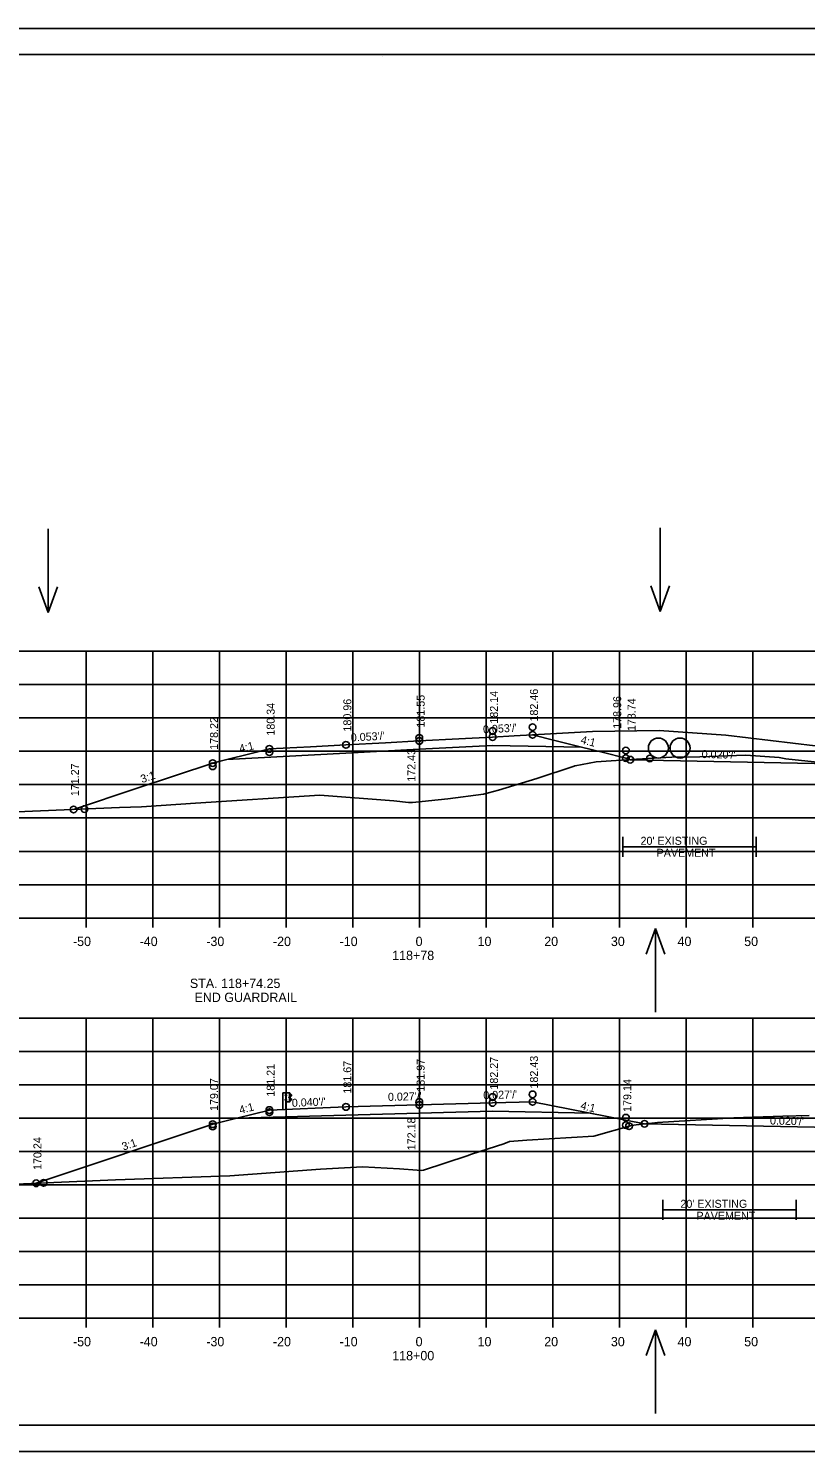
# Model space of a CAD drawing. Extents: x 915787 to 919910, y 133456 to 136717.
# Drawn here: x 916355.3 to 916471.9, y 135589.4 to 135802.7 of the extents above; entities that cross this region are included whole.
import ezdxf

# ---------------------------------------------------------------- set-up
doc = ezdxf.new("R2010")
doc.units = 0
for name, color, linetype in [('R_Axis', 7, 'Continuous'), ('R_Axis Annot', 7, 'Continuous'), ('R_Border', 7, 'Continuous'), ('R_Drive', 7, 'Continuous'), ('R_Exist Surface', 7, 'Continuous'), ('R_Exist Surface Annot', 7, 'Continuous'), ('R_Fin Surface', 7, 'Continuous'), ('R_Grid', 7, 'Continuous'), ('R_No Plot', 7, 'Continuous'), ('R_Proposed Road', 7, 'Continuous'), ('R_Water', 7, 'Continuous'), ('R_Water Annot', 7, 'Continuous'), ('R_Xsect Elev', 7, 'Continuous'), ('R_Xsect Slope', 7, 'Continuous')]:
    doc.layers.add(name, color=color, linetype=linetype)

msp = doc.modelspace()

# ---------------------------------------------------------------- linework, layer by layer
at = {"layer": 'R_Axis'}
for p, q in [((916273.98, 135669.39), (916553.98, 135669.39)), ((916363.98, 135667.99), (916363.98, 135669.39)), ((916373.98, 135667.99), (916373.98, 135669.39)), ((916383.98, 135667.99), (916383.98, 135669.39)), ((916393.98, 135667.99), (916393.98, 135669.39)), ((916403.98, 135667.99), (916403.98, 135669.39)), ((916413.98, 135667.99), (916413.98, 135669.39)), ((916423.98, 135667.99), (916423.98, 135669.39)), ((916433.98, 135667.99), (916433.98, 135669.39)), ((916443.98, 135667.99), (916443.98, 135669.39)), ((916453.98, 135667.99), (916453.98, 135669.39)), ((916463.98, 135667.99), (916463.98, 135669.39)), ((916273.98, 135609.39), (916553.98, 135609.39)), ((916363.98, 135607.99), (916363.98, 135609.39)), ((916373.98, 135607.99), (916373.98, 135609.39)), ((916383.98, 135607.99), (916383.98, 135609.39)), ((916393.98, 135607.99), (916393.98, 135609.39)), ((916403.98, 135607.99), (916403.98, 135609.39)), ((916413.98, 135607.99), (916413.98, 135609.39)), ((916423.98, 135607.99), (916423.98, 135609.39)), ((916433.98, 135607.99), (916433.98, 135609.39)), ((916443.98, 135607.99), (916443.98, 135609.39)), ((916453.98, 135607.99), (916453.98, 135609.39)), ((916463.98, 135607.99), (916463.98, 135609.39))]:
    msp.add_line(p, q, dxfattribs=at)
at = {"layer": 'R_Border'}
for p, q in [((916255.98, 135798.85), (916572.16, 135798.85)), ((916408.5, 135798.59), (916408.5, 135798.59)), ((916408.5, 135798.59), (916408.5, 135798.59)), ((916572.16, 135593.39), (916255.98, 135593.39))]:
    msp.add_line(p, q, dxfattribs=at)
at = {"layer": 'R_Drive'}
for q in [(916449.96, 135697.48), (916512.45, 135690.52)]:
    msp.add_line((916459.93, 135696.82), q, dxfattribs=at)
msp.add_lwpolyline([(916449.96, 135697.48), (916439.96, 135697.33), (916430.97, 135696.85)], dxfattribs=at)
at = {"layer": 'R_Exist Surface'}
for points in [[(916341.71, 135684.82), (916369.01, 135685.94), (916372.31, 135686.06), (916380.38, 135686.59), (916399.06, 135687.81), (916410.13, 135686.94), (916412.37, 135686.71), (916412.96, 135686.72), (916418.26, 135687.27), (916423.62, 135687.95), (916425.87, 135688.55), (916431.58, 135690.33), (916437.22, 135692.17), (916437.3, 135692.21), (916437.36, 135692.21), (916440.52, 135692.82), (916446.54, 135693.2), (916451.84, 135693.5), (916456.07, 135693.58), (916462.94, 135693.79), (916467.97, 135693.44), (916468.97, 135693.27), (916474.14, 135692.7)], [(916352.33, 135629.42), (916358.01, 135629.71), (916368.41, 135630.12), (916385.56, 135630.76), (916399.15, 135631.73), (916405.45, 135632.11), (916410.99, 135631.77), (916413.67, 135631.6), (916414.29, 135631.55), (916414.59, 135631.61), (916421.15, 135633.73), (916421.78, 135633.97), (916426.64, 135635.53), (916427.48, 135635.87), (916430.12, 135636.07), (916440.13, 135636.67), (916445.82, 135638.29), (916446.51, 135638.41), (916449.29, 135638.7), (916449.31, 135638.71), (916449.7, 135638.73), (916461.13, 135639.46), (916468.49, 135639.67), (916472.46, 135639.77)]]:
    msp.add_lwpolyline(points, dxfattribs=at)
at = {"layer": 'R_Exist Surface Annot'}
for p, q in [((916444.52, 135681.57), (916444.52, 135678.57)), ((916464.52, 135681.57), (916464.52, 135678.57)), ((916444.52, 135680.07), (916464.52, 135680.07)), ((916450.51, 135627.15), (916450.51, 135624.15)), ((916450.51, 135625.65), (916470.5, 135625.65)), ((916470.5, 135627.15), (916470.5, 135624.15))]:
    msp.add_line(p, q, dxfattribs=at)
at = {"layer": 'R_Fin Surface'}
for points in [[(916362.11, 135685.66), (916371.66, 135688.84), (916382.97, 135692.61), (916384.11, 135692.9), (916385.11, 135693.15), (916388.56, 135694.01), (916391.47, 135694.74), (916397.66, 135695.08), (916402.97, 135695.35), (916408.89, 135695.68), (916413.97, 135695.94), (916419.89, 135696.27), (916424.97, 135696.53), (916428.21, 135696.71), (916430.97, 135696.85), (916434.32, 135696.01), (916438.32, 135695.01), (916441.38, 135694.25), (916444.97, 135693.35), (916445.27, 135693.25), (916445.62, 135693.13), (916478.28, 135692.48)], [(916385.11, 135693.15), (916402.97, 135694.1), (916413.97, 135694.69), (916424.97, 135695.28), (916438.32, 135695.01)], [(916356.48, 135629.63), (916382.97, 135638.47), (916386.57, 135639.37), (916391.47, 135640.61), (916402.97, 135641.07), (916413.97, 135641.37), (916424.97, 135641.67), (916430.97, 135641.83), (916447.75, 135638.54), (916493.67, 135637.62)], [(916386.57, 135639.37), (916402.97, 135639.82), (916413.97, 135640.12), (916424.97, 135640.42), (916439.68, 135640.12)]]:
    msp.add_lwpolyline(points, dxfattribs=at)
at = {"layer": 'R_Grid'}
for p, q in [((916273.98, 135709.39), (916553.98, 135709.39)), ((916363.98, 135669.39), (916363.98, 135709.39)), ((916373.98, 135669.39), (916373.98, 135709.39)), ((916383.98, 135669.39), (916383.98, 135709.39)), ((916393.98, 135669.39), (916393.98, 135709.39)), ((916403.98, 135669.39), (916403.98, 135709.39)), ((916413.98, 135669.39), (916413.98, 135709.39)), ((916423.98, 135669.39), (916423.98, 135709.39)), ((916433.98, 135669.39), (916433.98, 135709.39)), ((916443.98, 135669.39), (916443.98, 135709.39)), ((916453.98, 135669.39), (916453.98, 135709.39)), ((916463.98, 135669.39), (916463.98, 135709.39)), ((916273.98, 135704.39), (916553.98, 135704.39)), ((916273.98, 135699.39), (916553.98, 135699.39)), ((916273.98, 135694.39), (916553.98, 135694.39)), ((916273.98, 135689.39), (916553.98, 135689.39)), ((916273.98, 135684.39), (916553.98, 135684.39)), ((916273.98, 135679.39), (916553.98, 135679.39)), ((916273.98, 135674.39), (916553.98, 135674.39)), ((916273.98, 135669.39), (916553.98, 135669.39)), ((916273.98, 135654.39), (916553.98, 135654.39)), ((916363.98, 135609.39), (916363.98, 135654.39)), ((916373.98, 135609.39), (916373.98, 135654.39)), ((916383.98, 135609.39), (916383.98, 135654.39)), ((916393.98, 135609.39), (916393.98, 135654.39)), ((916403.98, 135609.39), (916403.98, 135654.39)), ((916413.98, 135609.39), (916413.98, 135654.39)), ((916423.98, 135609.39), (916423.98, 135654.39)), ((916433.98, 135609.39), (916433.98, 135654.39)), ((916443.98, 135609.39), (916443.98, 135654.39)), ((916453.98, 135609.39), (916453.98, 135654.39)), ((916463.98, 135609.39), (916463.98, 135654.39)), ((916273.98, 135649.39), (916553.98, 135649.39)), ((916273.98, 135644.39), (916553.98, 135644.39)), ((916273.98, 135639.39), (916553.98, 135639.39)), ((916273.98, 135634.39), (916553.98, 135634.39)), ((916273.98, 135629.39), (916553.98, 135629.39)), ((916273.98, 135624.39), (916553.98, 135624.39)), ((916273.98, 135619.39), (916553.98, 135619.39)), ((916273.98, 135614.39), (916553.98, 135614.39)), ((916273.98, 135609.39), (916553.98, 135609.39))]:
    msp.add_line(p, q, dxfattribs=at)
at = {"layer": 'R_No Plot'}
for p, q in [((916243.57, 135802.75), (916576.91, 135802.75)), ((916243.57, 135589.42), (916576.91, 135589.42))]:
    msp.add_line(p, q, dxfattribs=at)
for points in [[(916243.57, 135802.75), (916576.91, 135802.75), (916576.91, 135589.41), (916243.57, 135589.41)], [(916489.9, 135798.85), (916489.9, 135788.97), (916525.63, 135788.97), (916525.63, 135786.05), (916548.83, 135786.05), (916548.83, 135762.84), (916572.16, 135762.84), (916572.16, 135593.39), (916255.98, 135593.39), (916255.98, 135798.85)]]:
    msp.add_lwpolyline(points, close=True, dxfattribs=at)
for centre in [(916424.97, 135697.43), (916430.97, 135698), (916402.97, 135695.35), (916402.97, 135695.35), (916413.97, 135696.39), (916413.97, 135695.94), (916424.97, 135696.53), (916430.97, 135696.85), (916391.47, 135694.74), (916391.47, 135694.27), (916444.97, 135694.5), (916444.97, 135693.35), (916445.62, 135693.13), (916448.54, 135693.31), (916382.97, 135692.61), (916382.97, 135692.14), (916362.11, 135685.66), (916363.73, 135685.73), (916413.97, 135641.81), (916424.97, 135642.56), (916430.97, 135642.96), (916430.97, 135641.83), (916391.47, 135640.61), (916391.47, 135640.29), (916402.97, 135641.07), (916402.97, 135641.07), (916413.97, 135641.37), (916424.97, 135641.67), (916382.97, 135638.47), (916382.97, 135638.15), (916444.97, 135639.46), (916444.97, 135638.33), (916445.43, 135638.18), (916447.75, 135638.54), (916356.48, 135629.63), (916357.61, 135629.69)]:
    msp.add_circle(centre, 0.5, dxfattribs=at)
at = {"layer": 'R_Proposed Road'}
for p, q in [((916393.47, 135643.2), (916393.47, 135640.68)), ((916393.5, 135643.2), (916393.5, 135640.68)), ((916393.86, 135642.1), (916393.86, 135642.19)), ((916393.87, 135642.79), (916393.87, 135642.88)), ((916393.92, 135642.21), (916393.87, 135642.21)), ((916393.93, 135642.9), (916393.88, 135642.9)), ((916393.93, 135642.87), (916393.88, 135642.87)), ((916393.93, 135642.8), (916393.88, 135642.8)), ((916393.93, 135642.77), (916393.88, 135642.77)), ((916393.93, 135642.8), (916393.89, 135642.8)), ((916393.92, 135642.08), (916393.92, 135642.21)), ((916394, 135643.2), (916393.93, 135643.2)), ((916393.93, 135642.77), (916393.93, 135642.9)), ((916393.97, 135640.68), (916393.97, 135643.2)), ((916394, 135643.2), (916393.99, 135643.2)), ((916394.05, 135642.83), (916394, 135642.83)), ((916394.01, 135642.89), (916394.06, 135642.89)), ((916394.01, 135642.77), (916394.06, 135642.77)), ((916394.06, 135642.21), (916394.01, 135642.21)), ((916394.06, 135642.89), (916394.06, 135642.77)), ((916394.06, 135642.08), (916394.06, 135642.21)), ((916394.43, 135642.47), (916394.43, 135642.56)), ((916394.49, 135642.58), (916394.44, 135642.58)), ((916394.49, 135642.55), (916394.44, 135642.55)), ((916394.49, 135642.48), (916394.44, 135642.48)), ((916394.49, 135642.48), (916394.44, 135642.48)), ((916394.49, 135642.45), (916394.44, 135642.45)), ((916394.49, 135642.45), (916394.49, 135642.58)), ((916394.5, 135641.83), (916394.5, 135643.19)), ((916394.64, 135642.99), (916394.53, 135643.05)), ((916394.63, 135642.97), (916394.54, 135643.02)), ((916394.54, 135642.45), (916394.54, 135642.58)), ((916394.56, 135642.45), (916394.56, 135642.58)), ((916394.58, 135642.65), (916394.76, 135642.76)), ((916394.73, 135642.28), (916394.58, 135642.38)), ((916394.75, 135642.3), (916394.59, 135642.4)), ((916394.6, 135642.63), (916394.77, 135642.74)), ((916394.76, 135642.87), (916394.63, 135642.97)), ((916394.77, 135642.88), (916394.64, 135642.99)), ((916393.92, 135642.18), (916393.87, 135642.18)), ((916393.92, 135642.11), (916393.87, 135642.11)), ((916393.92, 135642.08), (916393.87, 135642.08)), ((916393.92, 135642.11), (916393.88, 135642.11)), ((916394, 135641.83), (916393.96, 135641.83)), ((916394.05, 135642.15), (916394, 135642.15)), ((916394.06, 135642.08), (916394.01, 135642.08)), ((916394.53, 135642), (916394.63, 135642.05)), ((916394.53, 135641.98), (916394.65, 135642.03)), ((916394.63, 135642.05), (916394.76, 135642.16)), ((916394.65, 135642.03), (916394.77, 135642.14))]:
    msp.add_line(p, q, dxfattribs=at)
msp.add_lwpolyline([(916393.47, 135643.2), (916393.93, 135643.2), (916393.93, 135640.68)], dxfattribs=at)
for points in [[(916393.87, 135642.87), (916393.87, 135642.81), (916393.85, 135642.81), (916393.85, 135642.87)], [(916393.92, 135642.23), (916393.92, 135642.06), (916393.93, 135642.06), (916393.93, 135642.23)], [(916393.93, 135642.92), (916393.93, 135642.75), (916393.94, 135642.75), (916393.94, 135642.92)], [(916394.52, 135643.2), (916394.52, 135641.83), (916394, 135641.83), (916394, 135643.2)], [(916394.05, 135642.89), (916394.05, 135642.77), (916394, 135642.77), (916394, 135642.89)], [(916394.05, 135642.21), (916394.05, 135642.08), (916394, 135642.08), (916394, 135642.21)], [(916394.43, 135642.55), (916394.43, 135642.48), (916394.4, 135642.48), (916394.4, 135642.55)], [(916394.48, 135642.6), (916394.48, 135642.43), (916394.49, 135642.43), (916394.49, 135642.6)], [(916393.86, 135642.18), (916393.86, 135642.12), (916393.84, 135642.12), (916393.84, 135642.18)]]:
    msp.add_lwpolyline(points, close=True, dxfattribs=at)
for centre, radius, start, end in [((916393.89, 135642.19), 0.022, 134.5745, 222.2244), ((916393.9, 135642.88), 0.022, 134.5745, 222.2244), ((916393.97, 135642.84), 0.0922, 159.7423, 200.2577), ((916393.9, 135642.79), 0.025, 140.9334, 216.6234), ((916394.45, 135642.56), 0.022, 134.5745, 222.2244), ((916394.52, 135642.51), 0.0922, 159.7423, 200.2577), ((916394.46, 135642.47), 0.025, 140.9334, 216.6234), ((916394.63, 135642.58), 0.0865, 118.106, 175.0444), ((916394.61, 135642.44), 0.0703, 171.7804, 246.8536), ((916394.63, 135642.58), 0.0622, 118.106, 175.0444), ((916394.56, 135642.51), 0.0453, 282.9554, 86.0697), ((916394.61, 135642.44), 0.0462, 171.7804, 246.8536), ((916394.69, 135642.21), 0.0854, 325.2184, 59.12), ((916394.69, 135642.21), 0.109, 325.2184, 59.12), ((916394.73, 135642.81), 0.062, 299.2499, 57.9783), ((916394.73, 135642.81), 0.0856, 299.2499, 57.9783), ((916393.96, 135642.15), 0.0922, 159.7423, 200.2577), ((916393.89, 135642.1), 0.025, 140.9334, 216.6234)]:
    msp.add_arc(centre, radius, start, end, dxfattribs=at)
at = {"layer": 'R_Water'}
for centre in [(916449.83, 135694.88), (916453.08, 135694.88)]:
    msp.add_circle(centre, 1.5, dxfattribs=at)
at = {"layer": 'R_Water Annot'}
for p, q in [((916358.28, 135727.76), (916358.28, 135715.2)), ((916450.09, 135727.9), (916450.09, 135715.33)), ((916358.28, 135715.2), (916356.88, 135719.04)), ((916358.28, 135715.2), (916359.68, 135719.04)), ((916450.09, 135715.33), (916448.69, 135719.18)), ((916450.09, 135715.33), (916451.49, 135719.18)), ((916449.39, 135667.83), (916447.99, 135663.99)), ((916449.39, 135655.27), (916449.39, 135667.83)), ((916449.39, 135667.83), (916450.79, 135663.99)), ((916449.39, 135607.66), (916447.99, 135603.82)), ((916449.39, 135595.1), (916449.39, 135607.66)), ((916449.39, 135607.66), (916450.79, 135603.82))]:
    msp.add_line(p, q, dxfattribs=at)

# ---------------------------------------------------------------- texts
at = {"layer": 'R_Axis Annot'}
for s, p in [('-50', (916362.01, 135665.19)), ('-40', (916372.01, 135665.19)), ('-30', (916382.01, 135665.19)), ('-20', (916392.01, 135665.19)), ('-10', (916402.01, 135665.19)), ('0', (916413.41, 135665.19)), ('10', (916422.71, 135665.19)), ('20', (916432.71, 135665.19)), ('30', (916442.71, 135665.19)), ('40', (916452.71, 135665.19)), ('50', (916462.71, 135665.19)), ('118+78', (916409.9, 135663.09)), ('-50', (916362.01, 135605.19)), ('-40', (916372.01, 135605.19)), ('-30', (916382.01, 135605.19)), ('-20', (916392.01, 135605.19)), ('-10', (916402.01, 135605.19)), ('0', (916413.41, 135605.19)), ('10', (916422.71, 135605.19)), ('20', (916432.71, 135605.19)), ('30', (916442.71, 135605.19)), ('40', (916452.71, 135605.19)), ('50', (916462.71, 135605.19)), ('118+00', (916409.91, 135603.09))]:
    msp.add_text(s, height=1.4, dxfattribs=at).set_placement(p)
at = {"layer": 'R_Drive'}
for s, p in [('STA. 118+74.25', (916379.55, 135658.9)), ('END GUARDRAIL', (916380.24, 135656.8))]:
    msp.add_text(s, height=1.4, dxfattribs=at).set_placement(p)
at = {"layer": 'R_Exist Surface Annot'}
for s, p in [("20' EXISTING", (916447.16, 135680.37)), ('PAVEMENT', (916449.57, 135678.57)), ("20' EXISTING", (916453.14, 135625.95)), ('PAVEMENT', (916455.55, 135624.15))]:
    msp.add_text(s, height=1.2, dxfattribs=at).set_placement(p)
at = {"layer": 'R_Xsect Elev'}
for s, p in [('180.96', (916403.77, 135697.35)), ('181.55', (916414.77, 135697.94)), ('182.14', (916425.77, 135698.53)), ('182.46', (916431.77, 135698.85)), ('178.96', (916444.26, 135697.76)), ('178.74', (916446.41, 135697.41)), ('180.34', (916392.27, 135696.74)), ('178.22', (916383.77, 135694.61)), ('172.43', (916413.38, 135689.83)), ('171.27', (916362.91, 135687.66)), ('182.43', (916431.77, 135643.83)), ('181.21', (916392.27, 135642.61)), ('181.67', (916403.77, 135643.07)), ('181.97', (916414.77, 135643.37)), ('182.27', (916425.77, 135643.67)), ('179.07', (916383.77, 135640.47)), ('179.14', (916445.77, 135640.33)), ('172.18', (916413.38, 135634.58)), ('170.24', (916357.28, 135631.63))]:
    msp.add_text(s, height=1.2, rotation=90, dxfattribs=at).set_placement(p)
at = {"layer": 'R_Xsect Slope'}
for s, rotation, p in [("0.053'/'", 3.0607, (916423.56, 135697.06)), ('4:1', 14.0363, (916387.1, 135694.16)), ("0.053'/'", 3.0607, (916403.72, 135695.85)), ('4:1', 345.9637, (916438.09, 135695.59)), ("0.020'/'", 358.8542, (916456.32, 135693.38)), ('3:1', 18.435, (916372.38, 135689.61)), ("0.040'/'", 2.2906, (916394.87, 135641.08)), ("0.027'/'", 1.557, (916409.28, 135641.97)), ("0.027'/'", 1.557, (916423.58, 135642.23)), ('4:1', 14.1485, (916387.1, 135640.02)), ('4:1', 345.9638, (916438.07, 135640.78)), ("0.020'/'", 358.8542, (916466.57, 135638.44)), ('3:1', 18.4349, (916369.57, 135634.52))]:
    msp.add_text(s, height=1.2, rotation=rotation, dxfattribs=at).set_placement(p)

doc.saveas('drawing.dxf')
